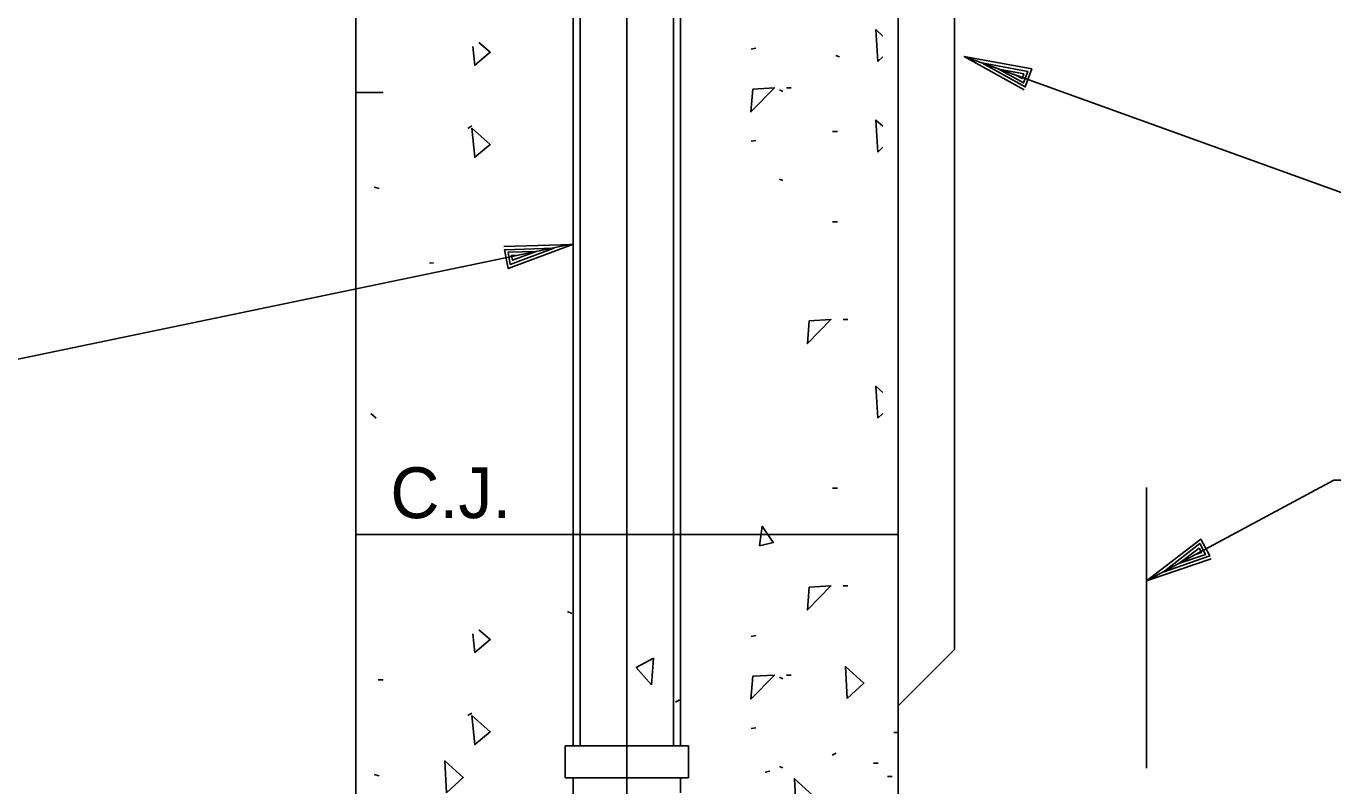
# Model space of a CAD drawing. Extents: x 22388.1 to 22405.7, y 22369.6 to 22390.4.
# Drawn here: x 22395.825 to 22397.03, y 22375.068 to 22375.768 of the extents above; entities that cross this region are included whole.
import ezdxf

# ---------------------------------------------------------------- set-up
doc = ezdxf.new("R2010")
doc.units = 0
for name, color, linetype in [('Level 1', 7, 'Continuous'), ('Level 2', 7, 'Continuous'), ('Level 4', 7, 'Continuous'), ('Level 44', 7, 'Continuous'), ('Level 7', 7, 'Continuous')]:
    doc.layers.add(name, color=color, linetype=linetype)

msp = doc.modelspace()

# ---------------------------------------------------------------- linework, layer by layer
at = {"layer": 'Level 1'}
for p, q in [((22396.3787, 22372.7735), (22396.3787, 22379.1804)), ((22396.8578, 22375.084), (22396.8578, 22375.3427))]:
    msp.add_line(p, q, dxfattribs=at)
at = {"layer": 'Level 2'}
for p, q in [((22396.3292, 22375.1046), (22396.3292, 22376.2175)), ((22396.3356, 22375.1046), (22396.3356, 22376.2175)), ((22396.4217, 22375.1046), (22396.4217, 22376.2175)), ((22396.4281, 22375.1046), (22396.4281, 22376.2175)), ((22396.6898, 22375.7403), (22396.6898, 22375.7403)), ((22396.7061, 22375.7344), (22396.7061, 22375.7344)), ((22396.3284, 22375.5668), (22396.3284, 22375.5668)), ((22396.3114, 22375.5635), (22396.3114, 22375.5635)), ((22396.6287, 22375.2993), (22396.1287, 22375.2993)), ((22396.8578, 22375.2566), (22396.8578, 22375.2566)), ((22396.8731, 22375.2648), (22396.8731, 22375.2648)), ((22396.3217, 22375.1046), (22396.4356, 22375.1046)), ((22396.3217, 22375.0749), (22396.3217, 22375.1046)), ((22396.4356, 22375.0749), (22396.4356, 22375.1046)), ((22396.3217, 22375.0749), (22396.4356, 22375.0749)), ((22396.3292, 22375.0547), (22396.3292, 22375.0749)), ((22396.4281, 22375.0612), (22396.4281, 22375.0749))]:
    msp.add_line(p, q, dxfattribs=at)
for points in [[(22397.4224, 22375.5079), (22397.3339, 22375.5079), (22396.6898, 22375.7403)], [(22396.745, 22375.7094), (22396.6898, 22375.7403), (22396.752, 22375.7288), (22396.746, 22375.7122), (22396.7061, 22375.7344), (22396.7483, 22375.7266), (22396.7445, 22375.7159), (22396.7218, 22375.7287), (22396.7447, 22375.7244), (22396.7431, 22375.72), (22396.7381, 22375.7229)], [(22395.5087, 22375.409), (22395.5861, 22375.4133), (22396.3273, 22375.5671)], [(22396.2652, 22375.565), (22396.3284, 22375.5668), (22396.2692, 22375.5447), (22396.2658, 22375.5621), (22396.3114, 22375.5635), (22396.2711, 22375.5485), (22396.269, 22375.5597), (22396.295, 22375.5603), (22396.2731, 22375.5523), (22396.2722, 22375.5569), (22396.278, 22375.557)], [(22397.1033, 22375.3496), (22397.0306, 22375.3496), (22396.8578, 22375.2566)], [(22396.9176, 22375.277), (22396.8578, 22375.2566), (22396.9078, 22375.2952), (22396.9162, 22375.2797), (22396.8731, 22375.2648), (22396.907, 22375.291), (22396.9124, 22375.2811), (22396.8878, 22375.2727), (22396.9063, 22375.2868), (22396.9085, 22375.2827), (22396.903, 22375.2809)]]:
    msp.add_lwpolyline(points, dxfattribs=at)
at = {"layer": 'Level 44'}
for p, q in [((22396.4932, 22375.7471), (22396.4975, 22375.7479)), ((22396.5714, 22375.7412), (22396.5747, 22375.74)), ((22396.5259, 22375.7114), (22396.5302, 22375.7114)), ((22396.1287, 22375.7071), (22396.1538, 22375.7071)), ((22396.5193, 22375.7094), (22396.5226, 22375.7081)), ((22396.232, 22375.674), (22396.2357, 22375.6763)), ((22396.5683, 22375.6712), (22396.5728, 22375.6712)), ((22396.4932, 22375.6621), (22396.4975, 22375.6629)), ((22396.5193, 22375.6271), (22396.5226, 22375.6258)), ((22396.1457, 22375.6199), (22396.1502, 22375.6186)), ((22396.5683, 22375.5878), (22396.5728, 22375.5878)), ((22396.1967, 22375.55), (22396.2004, 22375.5497)), ((22396.578, 22375.4977), (22396.5823, 22375.4977)), ((22396.5683, 22375.3422), (22396.5728, 22375.3422)), ((22396.578, 22375.252), (22396.5823, 22375.252)), ((22396.324, 22375.2285), (22396.328, 22375.2265)), ((22396.4932, 22375.2054), (22396.4975, 22375.2062)), ((22396.5259, 22375.1698), (22396.5302, 22375.1698)), ((22396.1493, 22375.1654), (22396.1538, 22375.1654)), ((22396.5193, 22375.1677), (22396.5226, 22375.1664)), ((22396.4234, 22375.1448), (22396.4272, 22375.147)), ((22396.232, 22375.1324), (22396.2357, 22375.1346)), ((22396.4932, 22375.1204), (22396.4975, 22375.1212)), ((22396.6248, 22375.1167), (22396.6293, 22375.1167)), ((22396.5681, 22375.0959), (22396.5716, 22375.0976)), ((22396.5193, 22375.0854), (22396.5226, 22375.0842)), ((22396.606, 22375.0884), (22396.6105, 22375.0884)), ((22396.1457, 22375.0782), (22396.1502, 22375.0769)), ((22396.5061, 22375.0802), (22396.5104, 22375.081)), ((22396.6189, 22375.0763), (22396.6234, 22375.0763))]:
    msp.add_line(p, q, dxfattribs=at)
for points in [[(22396.6148, 22375.7592), (22396.6083, 22375.7651), (22396.61, 22375.7356)], [(22396.2422, 22375.7533), (22396.2526, 22375.7442), (22396.2384, 22375.7323), (22396.2365, 22375.7495)], [(22396.61, 22375.7356), (22396.6148, 22375.7401)], [(22396.6148, 22375.6759), (22396.6083, 22375.6817), (22396.61, 22375.6522)], [(22396.61, 22375.6522), (22396.6148, 22375.6567)], [(22396.6148, 22375.4303), (22396.6083, 22375.4361), (22396.61, 22375.4066)], [(22396.1473, 22375.4066), (22396.1425, 22375.4111)], [(22396.61, 22375.4066), (22396.6148, 22375.4111)], [(22396.2422, 22375.2116), (22396.2526, 22375.2025), (22396.2384, 22375.1906), (22396.2365, 22375.2079)]]:
    msp.add_lwpolyline(points, dxfattribs=at)
for points in [[(22396.4947, 22375.7103), (22396.5147, 22375.7114), (22396.493, 22375.6892)], [(22396.2355, 22375.6741), (22396.2526, 22375.6592), (22396.2384, 22375.6473)], [(22396.5468, 22375.4966), (22396.5668, 22375.4977), (22396.5451, 22375.4755)], [(22396.501, 22375.2889), (22396.5033, 22375.3071), (22396.5136, 22375.2919)], [(22396.5468, 22375.2509), (22396.5668, 22375.252), (22396.5451, 22375.2299)], [(22396.4014, 22375.1608), (22396.3872, 22375.1768), (22396.4031, 22375.1853)], [(22396.4947, 22375.1687), (22396.5147, 22375.1698), (22396.493, 22375.1476)], [(22396.5818, 22375.1481), (22396.5972, 22375.1624), (22396.5801, 22375.1776)], [(22396.2355, 22375.1324), (22396.2526, 22375.1175), (22396.2384, 22375.1056)], [(22396.2123, 22375.0611), (22396.2277, 22375.0754), (22396.2106, 22375.0906)], [(22396.5348, 22375.0446), (22396.5502, 22375.0588), (22396.5331, 22375.0741)]]:
    msp.add_lwpolyline(points, close=True, dxfattribs=at)
at = {"layer": 'Level 7'}
for p, q in [((22396.1287, 22374.6326), (22396.1287, 22376.2749)), ((22396.6287, 22374.6326), (22396.6287, 22376.2749)), ((22396.6808, 22375.1935), (22396.6808, 22375.9467)), ((22396.6287, 22375.1414), (22396.6808, 22375.1935))]:
    msp.add_line(p, q, dxfattribs=at)

# ---------------------------------------------------------------- texts
at = {"layer": 'Level 4'}
msp.add_text('C.J.', height=0.04688, dxfattribs=at).set_placement((22396.1605, 22375.3145))

doc.saveas('drawing.dxf')
